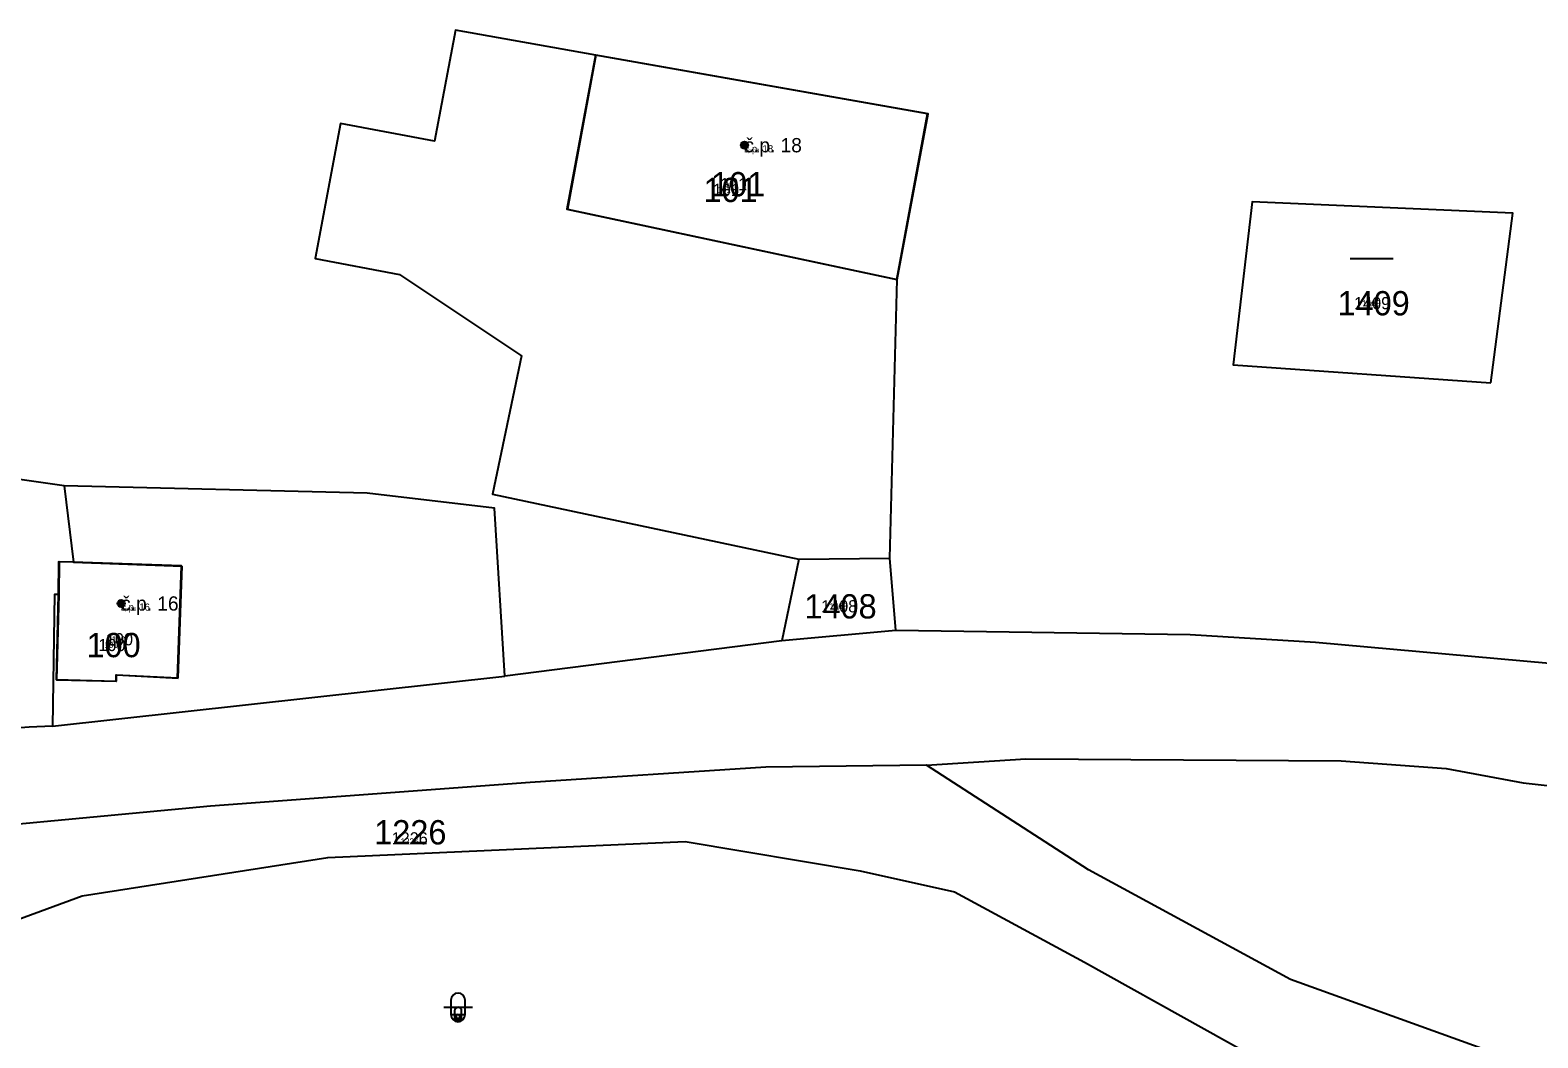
# Model space of a CAD drawing. Extents: x -744652 to -739090, y -980828 to -975855.
# Drawn here: x -740368.1 to -740262.6, y -979289.3 to -979218.8 of the extents above; entities that cross this region are included whole.
import ezdxf

# ---------------------------------------------------------------- set-up
doc = ezdxf.new("R2010")
doc.units = 0
for name, color, linetype in [('KAT_02_hranice parcel', 7, 'Continuous'), ('KAT_03_1000_st čísla parcelní', 7, 'Continuous'), ('KAT_03_1000_čísla parcelní', 7, 'Continuous'), ('KAT_03_1000_čísla popisná', 7, 'Continuous'), ('KAT_03_100_st čísla parcelní', 7, 'Continuous'), ('KAT_03_100_čísla parcelní', 7, 'Continuous'), ('KAT_03_100_čísla popisná', 7, 'Continuous'), ('KAT_03_250_st čísla parcelní', 7, 'Continuous'), ('KAT_03_250_čísla parcelní', 7, 'Continuous'), ('KAT_03_250_čísla popisná', 7, 'Continuous'), ('KAT_03_500_st čísla parcelní', 7, 'Continuous'), ('KAT_03_500_čísla parcelní', 7, 'Continuous'), ('KAT_03_500_čísla popisná', 7, 'Continuous'), ('KAT_04_vnitřní kresba', 7, 'Continuous'), ('KAT_05_1000_značky kultur', 7, 'Continuous'), ('KAT_05_100_značky kultur', 7, 'Continuous'), ('KAT_05_250_značky kultur', 7, 'Continuous'), ('KAT_05_500_značky kultur', 7, 'Continuous'), ('KAT_07_1000_značky budov', 7, 'Continuous'), ('KAT_07_100_značky budov', 7, 'Continuous'), ('KAT_07_500_značky budov', 7, 'Continuous'), ('KAT_14_plocha_budovy', 7, 'Continuous')]:
    doc.layers.add(name, color=color, linetype=linetype)

msp = doc.modelspace()

# ---------------------------------------------------------------- linework, layer by layer
at = {"layer": 'KAT_02_hranice parcel'}
for p, q in [((-740314.33, -979255.78), (-740315.52, -979261.5)), ((-740314.33, -979255.78), (-740307.98, -979255.72)), ((-740307.54, -979260.76), (-740307.98, -979255.72)), ((-740315.52, -979261.5), (-740334.91, -979263.97)), ((-740307.54, -979260.76), (-740315.52, -979261.5)), ((-740366.56, -979267.47), (-740334.91, -979263.97))]:
    msp.add_line(p, q, dxfattribs=at)
for points in [[(-740307.98, -979255.72), (-740307.45, -979236.21), (-740305.29, -979224.62), (-740328.53, -979220.51), (-740338.37, -979218.76), (-740339.82, -979226.54), (-740346.41, -979225.3), (-740348.17, -979234.74), (-740342.27, -979235.85), (-740333.73, -979241.54), (-740335.78, -979251.23), (-740314.33, -979255.78)], [(-740265.91, -979243.43), (-740264.37, -979231.56), (-740282.62, -979230.77), (-740283.95, -979242.19), (-740265.91, -979243.43)], [(-740365.74, -979250.65), (-740376.85, -979249.07), (-740404.58, -979245.01), (-740407, -979244.83), (-740422.47, -979263.1)], [(-740365.74, -979250.65), (-740365.09, -979256), (-740366.09, -979255.97), (-740366.11, -979258.25), (-740366.42, -979258.24), (-740366.56, -979267.47)], [(-740334.91, -979263.97), (-740335.63, -979252.21), (-740344.53, -979251.16), (-740365.74, -979250.65)], [(-740256.35, -979263.57), (-740278.18, -979261.6), (-740286.96, -979261.07), (-740307.54, -979260.76)], [(-740366.56, -979267.47), (-740368.2, -979267.54), (-740386.27, -979268.89), (-740396.16, -979268.91), (-740400.31, -979268.68), (-740408.06, -979268.1), (-740422.47, -979263.1)], [(-740305.4, -979270.19), (-740298.46, -979269.74), (-740276.4, -979269.89), (-740269.04, -979270.42), (-740263.66, -979271.44), (-740239.95, -979274.07), (-740235.37, -979273.98), (-740227.99, -979279.39)], [(-740305.4, -979270.19), (-740316.64, -979270.33), (-740333.14, -979271.4), (-740355.51, -979273.06), (-740379.33, -979275.31)], [(-740226.75, -979311.6), (-740228.53, -979309.59), (-740238.98, -979306.78), (-740249.17, -979301.48), (-740259.31, -979294.12), (-740266.55, -979290.03), (-740279.94, -979285.19), (-740294.08, -979277.53), (-740305.4, -979270.19)], [(-740406.97, -979295.62), (-740405.55, -979295.03), (-740398.05, -979293.93), (-740375.97, -979283.57), (-740364.47, -979279.33), (-740347.29, -979276.66), (-740322.3, -979275.53), (-740310.04, -979277.59), (-740303.44, -979279.06), (-740294.35, -979283.98), (-740269.22, -979297.98)]]:
    msp.add_lwpolyline(points, dxfattribs=at)
at = {"layer": 'KAT_03_1000_čísla popisná'}
for centre in [(-740318.14, -979226.81), (-740361.75, -979258.88)]:
    msp.add_circle(centre, 0.25, dxfattribs=at)
at = {"layer": 'KAT_03_100_čísla popisná'}
for centre in [(-740318.14, -979226.81), (-740361.75, -979258.88)]:
    msp.add_circle(centre, 0.025, dxfattribs=at)
at = {"layer": 'KAT_03_250_čísla popisná'}
for centre in [(-740318.14, -979226.81), (-740361.75, -979258.88)]:
    msp.add_circle(centre, 0.0625, dxfattribs=at)
at = {"layer": 'KAT_03_500_čísla popisná'}
for centre in [(-740318.14, -979226.81), (-740361.75, -979258.88)]:
    msp.add_circle(centre, 0.125, dxfattribs=at)
at = {"layer": 'KAT_04_vnitřní kresba'}
for p, q in [((-740328.53, -979220.51), (-740330.52, -979231.29)), ((-740330.52, -979231.29), (-740307.45, -979236.21)), ((-740365.09, -979256), (-740357.49, -979256.26)), ((-740357.76, -979264.1), (-740357.49, -979256.26)), ((-740366.11, -979258.25), (-740366.27, -979264.22)), ((-740366.27, -979264.22), (-740362.07, -979264.32)), ((-740362.07, -979264.32), (-740362.07, -979263.88)), ((-740362.07, -979263.88), (-740357.76, -979264.1))]:
    msp.add_line(p, q, dxfattribs=at)
at = {"layer": 'KAT_05_1000_značky kultur'}
for p, q in [((-740275.76, -979234.74), (-740272.76, -979234.74)), ((-740338.68, -979286.64), (-740338.68, -979287.64)), ((-740337.68, -979287.64), (-740337.68, -979286.64)), ((-740339.18, -979287.14), (-740337.18, -979287.14))]:
    msp.add_line(p, q, dxfattribs=at)
for centre, start, end in [((-740338.18, -979286.64), 0, 180), ((-740338.18, -979287.64), 180, 359.9879)]:
    msp.add_arc(centre, 0.5, start, end, dxfattribs=at)
at = {"layer": 'KAT_05_100_značky kultur'}
for p, q in [((-740274.41, -979234.74), (-740274.11, -979234.74)), ((-740338.28, -979288.04), (-740338.08, -979288.04)), ((-740338.23, -979287.99), (-740338.23, -979288.09)), ((-740338.13, -979288.09), (-740338.13, -979287.99))]:
    msp.add_line(p, q, dxfattribs=at)
for centre, start, end in [((-740338.18, -979287.99), 0, 180), ((-740338.18, -979288.09), 180, 359.9879)]:
    msp.add_arc(centre, 0.05, start, end, dxfattribs=at)
at = {"layer": 'KAT_05_250_značky kultur'}
for p, q in [((-740274.63, -979234.74), (-740273.88, -979234.74)), ((-740338.43, -979287.89), (-740337.93, -979287.89)), ((-740338.31, -979287.77), (-740338.31, -979288.02)), ((-740338.05, -979288.02), (-740338.05, -979287.77))]:
    msp.add_line(p, q, dxfattribs=at)
for centre, start, end in [((-740338.18, -979287.77), 0, 180), ((-740338.18, -979288.02), 180, 359.9879)]:
    msp.add_arc(centre, 0.125, start, end, dxfattribs=at)
at = {"layer": 'KAT_05_500_značky kultur'}
for p, q in [((-740275.01, -979234.74), (-740273.51, -979234.74)), ((-740338.68, -979287.64), (-740337.68, -979287.64)), ((-740338.43, -979287.39), (-740338.43, -979287.89)), ((-740337.93, -979287.89), (-740337.93, -979287.39))]:
    msp.add_line(p, q, dxfattribs=at)
for centre, start, end in [((-740338.18, -979287.39), 0, 180), ((-740338.18, -979287.89), 180, 359.9879)]:
    msp.add_arc(centre, 0.25, start, end, dxfattribs=at)
at = {"layer": 'KAT_07_1000_značky budov'}
for centre in [(-740318.15, -979226.81), (-740361.76, -979258.88)]:
    msp.add_circle(centre, 0.175, dxfattribs=at)
at = {"layer": 'KAT_07_100_značky budov'}
for centre in [(-740318.14, -979226.81), (-740361.75, -979258.88)]:
    msp.add_circle(centre, 0.0175, dxfattribs=at)
at = {"layer": 'KAT_07_500_značky budov'}
for centre in [(-740318.14, -979226.81), (-740361.75, -979258.88)]:
    msp.add_circle(centre, 0.0875, dxfattribs=at)
at = {"layer": 'KAT_14_plocha_budovy'}
for points in [[(-740328.57, -979220.5), (-740330.56, -979231.28), (-740307.49, -979236.2), (-740305.33, -979224.61)], [(-740366.15, -979258.24), (-740366.31, -979264.21), (-740362.11, -979264.31), (-740362.11, -979263.87), (-740357.8, -979264.09), (-740357.53, -979256.25), (-740365.13, -979255.99), (-740366.13, -979255.96)]]:
    msp.add_lwpolyline(points, close=True, dxfattribs=at)

# ---------------------------------------------------------------- texts
at = {"layer": 'KAT_03_1000_st čísla parcelní'}
for s, p in [('101', (-740321.01, -979230.79)), ('100', (-740364.18, -979262.64))]:
    msp.add_text(s, height=1.7, dxfattribs=at).set_placement(p)
at = {"layer": 'KAT_03_1000_čísla parcelní'}
for s, p in [('101', (-740320.48, -979230.39)), ('1409', (-740276.65, -979238.72)), ('1408', (-740313.95, -979259.93)), ('1226', (-740344.05, -979275.74))]:
    msp.add_text(s, height=1.7, dxfattribs=at).set_placement(p)
at = {"layer": 'KAT_03_1000_čísla popisná'}
for s, p in [('č.p. 18', (-740318.14, -979227.31)), ('č.p. 16', (-740361.75, -979259.38))]:
    msp.add_text(s, height=1, dxfattribs=at).set_placement(p)
at = {"layer": 'KAT_03_100_st čísla parcelní'}
for s, p in [('101', (-740319.85, -979230.02)), ('100', (-740362.68, -979261.87))]:
    msp.add_text(s, height=0.17, dxfattribs=at).set_placement(p)
at = {"layer": 'KAT_03_100_čísla parcelní'}
for s, p in [('101', (-740319.33, -979229.62)), ('1409', (-740274.56, -979237.95)), ('1408', (-740311.84, -979259.16)), ('100', (-740362.16, -979261.47)), ('1226', (-740341.85, -979275.74))]:
    msp.add_text(s, height=0.17, dxfattribs=at).set_placement(p)
at = {"layer": 'KAT_03_100_čísla popisná'}
for s, p in [('č.p. 18', (-740318.14, -979227.31)), ('č.p. 16', (-740361.75, -979259.38))]:
    msp.add_text(s, height=0.1, dxfattribs=at).set_placement(p)
at = {"layer": 'KAT_03_250_st čísla parcelní'}
for s, p in [('101', (-740320.04, -979230.15)), ('100', (-740362.93, -979262))]:
    msp.add_text(s, height=0.425, dxfattribs=at).set_placement(p)
at = {"layer": 'KAT_03_250_čísla parcelní'}
for s, p in [('101', (-740319.52, -979229.75)), ('1409', (-740274.91, -979238.08)), ('1408', (-740312.19, -979259.29)), ('100', (-740362.41, -979261.6)), ('1226', (-740342.21, -979275.74))]:
    msp.add_text(s, height=0.425, dxfattribs=at).set_placement(p)
at = {"layer": 'KAT_03_250_čísla popisná'}
for s, p in [('č.p. 18', (-740318.14, -979227.31)), ('č.p. 16', (-740361.75, -979259.38))]:
    msp.add_text(s, height=0.25, dxfattribs=at).set_placement(p)
at = {"layer": 'KAT_03_500_st čísla parcelní'}
for s, p in [('101', (-740320.36, -979230.36)), ('100', (-740363.35, -979262.21))]:
    msp.add_text(s, height=0.85, dxfattribs=at).set_placement(p)
at = {"layer": 'KAT_03_500_čísla parcelní'}
for s, p in [('101', (-740319.84, -979229.96)), ('1409', (-740275.49, -979238.29)), ('1408', (-740312.78, -979259.5)), ('100', (-740362.82, -979261.81)), ('1226', (-740342.83, -979275.74))]:
    msp.add_text(s, height=0.85, dxfattribs=at).set_placement(p)
at = {"layer": 'KAT_03_500_čísla popisná'}
for s, p in [('č.p. 18', (-740318.14, -979227.31)), ('č.p. 16', (-740361.75, -979259.38))]:
    msp.add_text(s, height=0.5, dxfattribs=at).set_placement(p)

doc.saveas('drawing.dxf')
